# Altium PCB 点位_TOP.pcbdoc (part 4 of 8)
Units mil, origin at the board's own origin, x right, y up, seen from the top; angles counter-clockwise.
Board outline 5129 x 4161 mil, 8 copper layers (Top Layer, GND1, 内层2, VCC, 内层4, Inner5, GND2, Bottom Layer); 288 components, 452 nets, 2040 pads, 1119 vias.
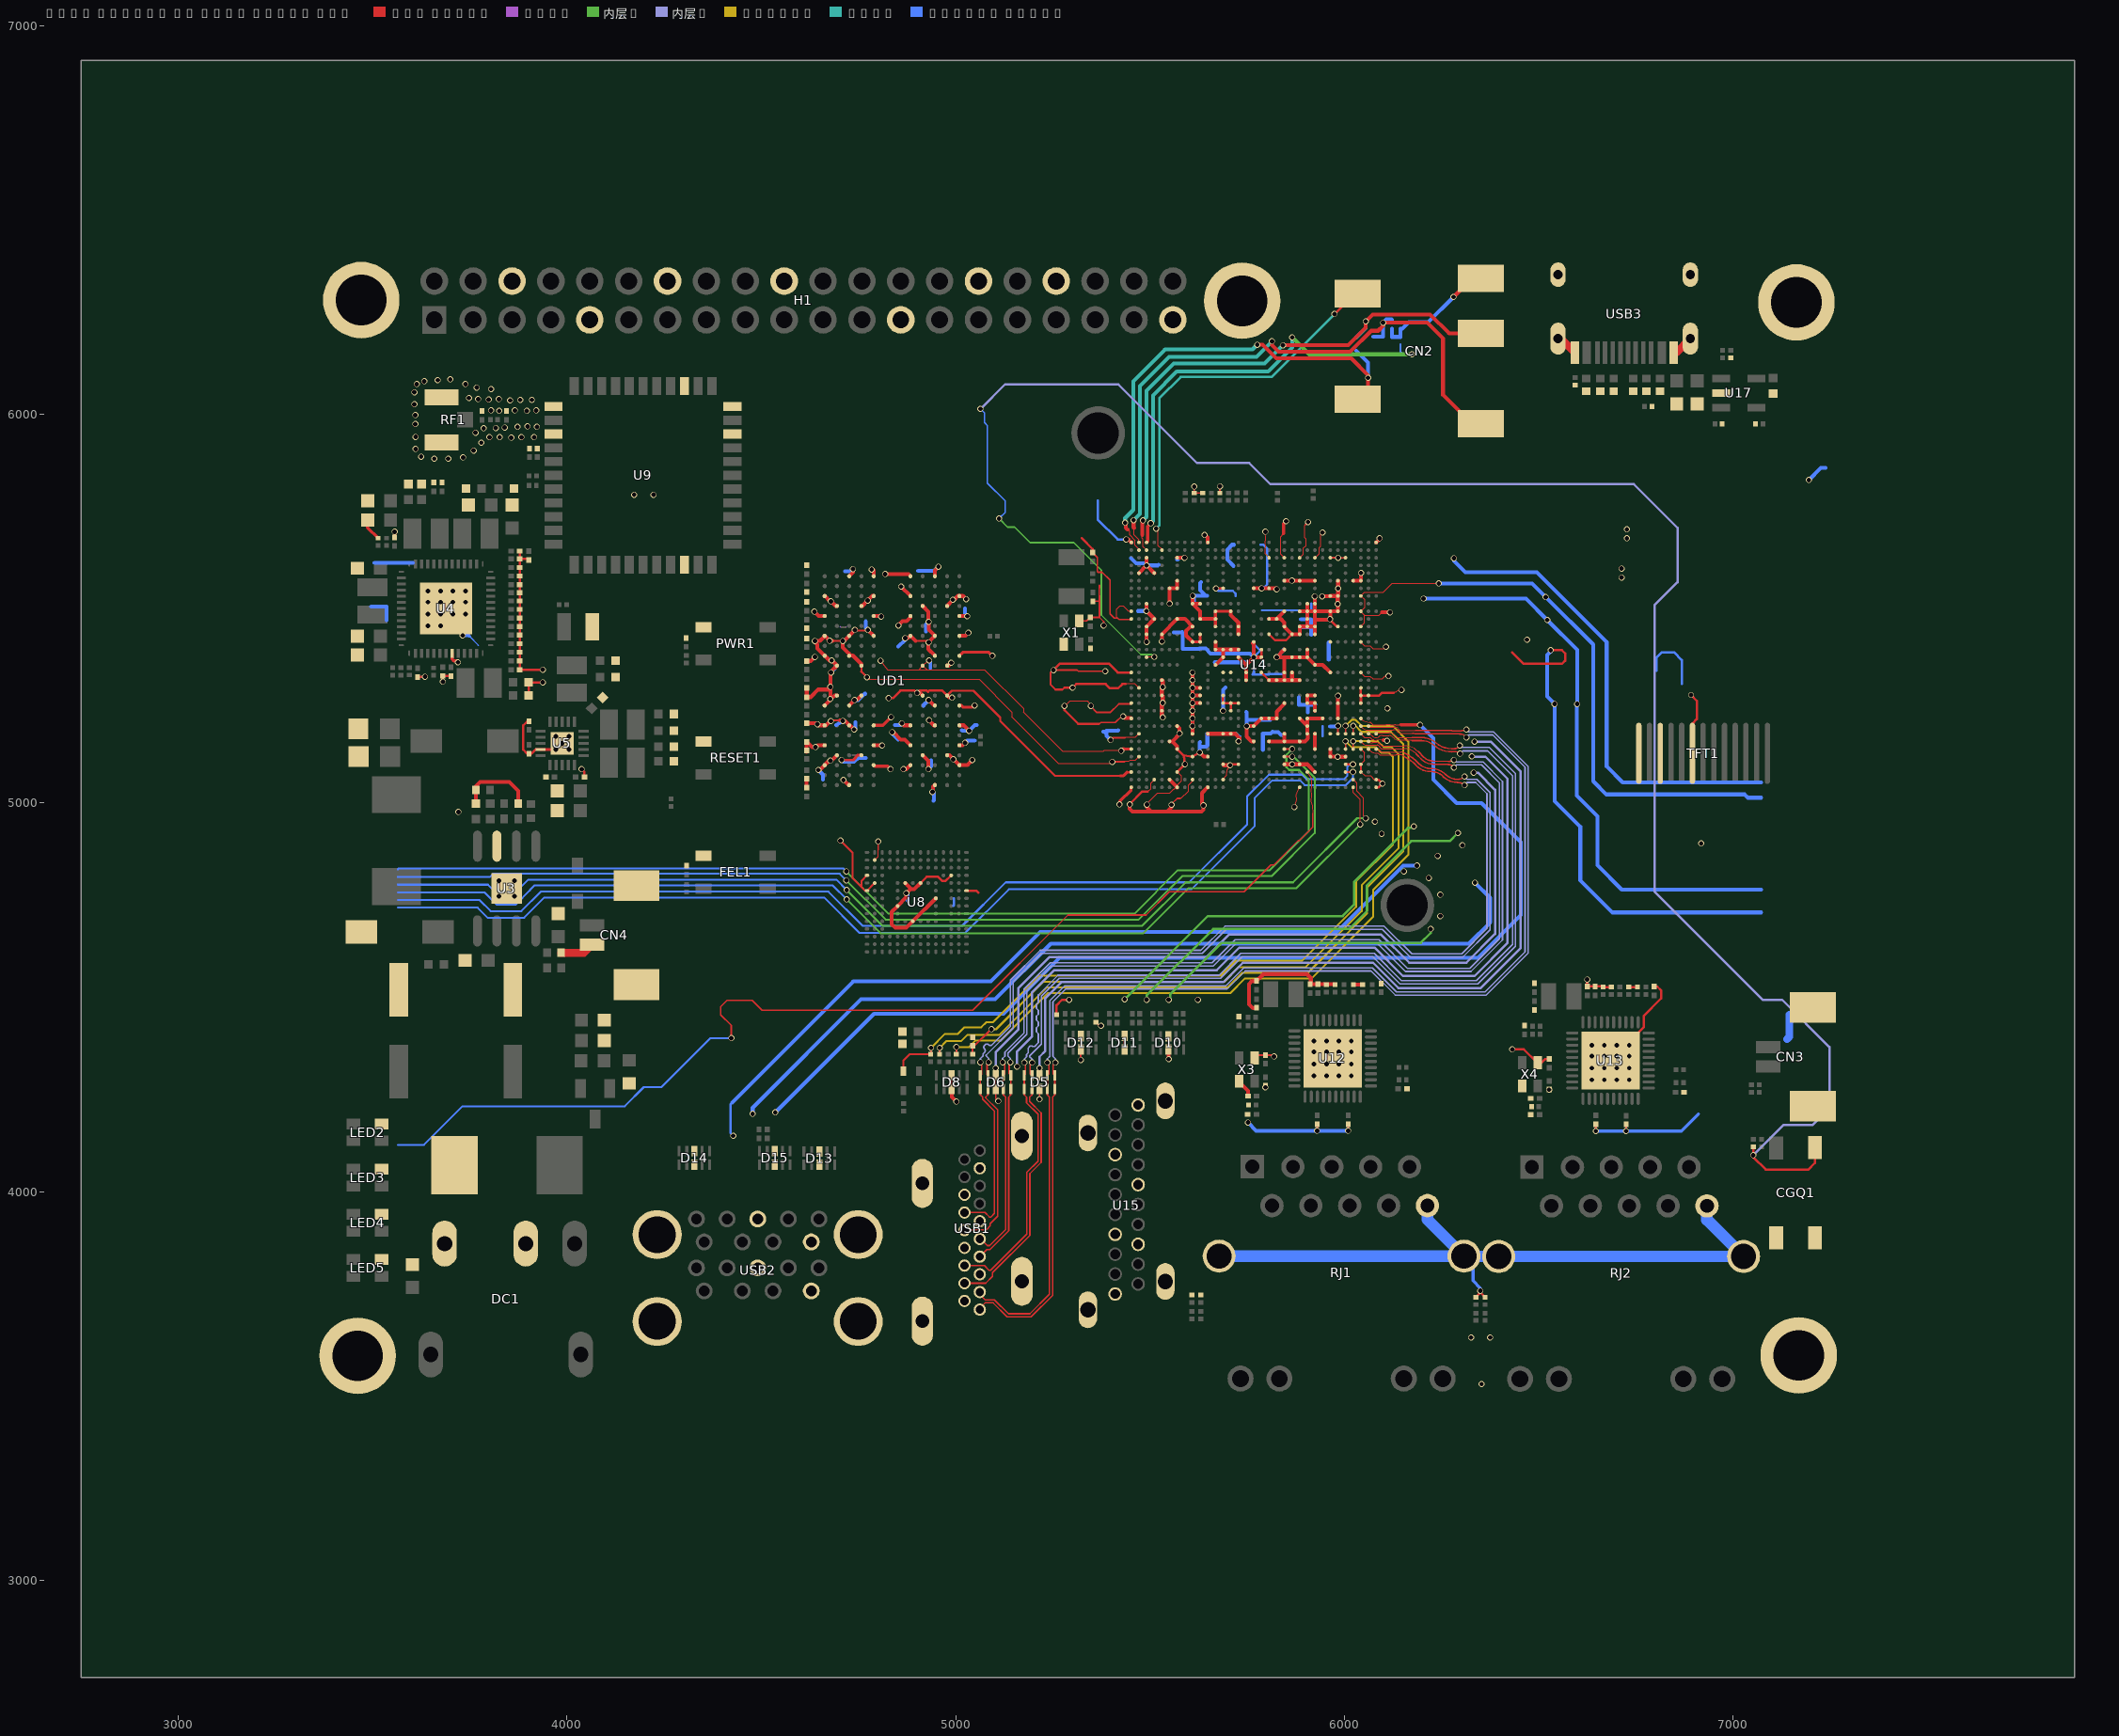
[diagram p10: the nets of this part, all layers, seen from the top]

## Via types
v1: diameter 15.75, hole 11.8, Top Layer to Bottom Layer, 496 vias
v2: diameter 15.7, hole 11.8, Top Layer to Bottom Layer, 335 vias
v3: diameter 15.75, hole 11.81, Top Layer to Bottom Layer, 279 vias
v4: diameter 24, hole 12, Top Layer to Bottom Layer, 9 vias

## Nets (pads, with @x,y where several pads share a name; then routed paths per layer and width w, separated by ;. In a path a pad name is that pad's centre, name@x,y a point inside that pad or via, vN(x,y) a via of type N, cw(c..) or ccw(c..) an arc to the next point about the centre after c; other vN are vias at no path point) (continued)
GND: C1.1 C2.1 C3.1 C5.1 C6.1 C7.1 C8.1 C10.2 C11.2 C12.2 C15.1 C16.1 C17.2 C18.1 C25.1 C27.1 C28.1 C31.1 C33.1 C35.1 C43.2 C44.1 C45.1 C51.2 C52.2 C53.2 C54.2 C55.2 C59.2 C60.1 C61.2 C62.1 C63.2 C64.1 C65.2 C66.1 C69.2 C70.1 C71.2 C72.1 C73.2 C74.1 C80.1 C81.1 C87.1 C88.2 C89.1 C95.1 C96.1 C97.1 C98.1 C99.1 C100.1 C101.1 C131.1 C136.1 C139.1 C140.1 C146.1 C147.2 C148.1 C149.1 C150.1 C157.1 C158.1 C159.1 C160.1 C179.1 C180.1 C189.1 C210.1 C218.1 C221.1 C222.1 C244.1 C245.1 C249.2 C250.2 C251.1 C252.1 C253.2 C254.2 C256.2 C257.1 C258.2 C259.1 C260.2 C261.2 C262.2 C263.2 C264.2 C265.2 C266.2 C267.2 C268.1 C269.2 C270.2 C271.2 C272.2 C273.2 C274.2 C275.1 C280.1 C281.1 C282.1 C283.1 C284.1 C290.1 C291.1 C292.1 C293.1 CGQ1.1 CGQ1.2 CN3.3 CN3.4 CN4.1 CN4.3 CN4.4 D2.1 D4.1 D5.3 D5.8 D6.3 D6.8 D8.3 D8.8 D10.3 D10.8 D11.3 D11.8 D12.3 D12.8 D13.3 D13.8 D14.3 D14.8 D15.3 D15.8 D24.1 D25.1 D26.1 D27.1 D30.1 D31.1 DC1.2 DC1.3 FEL1.1 H1.6 H1.9 H1.14 H1.20 H1.25 H1.30 H1.34 H1.39 LED1.2 LED2.2 LED3.2 LED4.2 LED5.2 pad.54 PWR1.1 R2.1 R6.1 R7.2 R8.1 R13.1 R33.1 R34.1 R35.1 R60.1 R62.1 R82.1 R85.1 R86.1 R93.1 R94.1 R95.1 R96.1 R100.1 R103.1 R104.1 R111.1 R112.1 R113.1 R114.1 R117.2 R118.1 R121.1 R129.1 R130.1 RESET1.1 RF1.2 RF1.3 RJ1.P10 RJ1.SHIELD0 RJ1.SHIELD1 RJ2.P10 RJ2.SHIELD0 RJ2.SHIELD1 TFT1.8 TFT1.11 TFT1.13 U1.2 U2.2 U3.7 U3.9 U4.8 U4.53 U5.9 U5.21 U8.A6 U8.C4 U8.E7 U8.G5 U8.H10 U8.J5 U8.K8 U8.N2 U8.N5 U8.P4 U8.P6 U9.1 U9.3 U9.20 U9.31 U9.33 U9.36 U12.41 U13.41 U14.A1 U14.A32 U14.A33 U14.AA7 U14.AA15 U14.AA16 U14.AA18 U14.AA21 U14.AA22 U14.AA26 U14.AA30 U14.AA32 U14.AB10 U14.AB11 U14.AB12 U14.AB14 U14.AB15 U14.AB17 U14.AC1 U14.AC26 U14.AC29 U14.AC33 U14.AD9 U14.AD11 U14.AD13 U14.AD14 U14.AD20 U14.AD21 U14.AD22 U14.AE9 U14.AE12 U14.AE14 U14.AE18 U14.AE19 U14.AE20 U14.AE21 U14.AE22 U14.AE23 U14.AE24 U14.AE25 U14.AE26 U14.AE29 U14.AE32 U14.AG3 U14.AG6 U14.AG7 U14.AG11 U14.AG25 U14.AG28 U14.AG31 U14.AG33 U14.AH7 U14.AH9 U14.AH27 U14.AH32 U14.AJ13 U14.AJ19 U14.AJ21 U14.AJ23 U14.AK5 U14.AK11 U14.AK32 U14.AL3 U14.AL9 U14.AL12 U14.AL13 U14.AL14 U14.AM5 U14.AM20 U14.AM26 U14.AM29 U14.AN1 U14.AN10 U14.AN11 U14.AN18 U14.AN22 U14.AN24 U14.AN28 U14.AN31 U14.AN33 U14.B21 U14.C6 U14.C8 U14.C10 U14.C12 U14.C14 U14.C18 U14.C20 U14.C21 U14.C22 U14.C24 U14.C26 U14.C28 U14.C30 U14.C31 U14.D6 U14.E3 U14.E29 U14.F6 U14.F8 U14.F10 U14.F12 U14.F22 U14.F24 U14.G3 U14.G8 U14.G10 U14.G14 U14.G18 U14.G26 U14.G28 U14.G29 U14.H24 U14.J3 U14.J6 U14.J9 U14.J10 U14.J12 U14.J13 U14.J17 U14.J21 U14.J22 U14.J23 U14.J26 U14.J28 U14.J31 U14.K9 U14.K10 U14.K11 U14.K12 U14.K15 U14.K16 U14.K21 U14.K22 U14.K24 U14.K25 U14.K26 U14.L3 U14.L6 U14.L10 U14.L12 U14.L13 U14.L16 U14.L19 U14.L24 U14.L27 U14.L30 U14.L33 U14.M13 U14.M16 U14.M18 U14.M19 U14.N3 U14.N6 U14.N10 U14.N12 U14.N15 U14.N18 U14.N19 U14.N22 U14.N26 U14.N27 U14.N30 U14.P11 U14.P16 U14.P19 U14.P24 U14.R3 U14.R7 U14.R11 U14.R13 U14.R19 U14.R24 U14.R27 U14.T15 U14.T16 U14.T18 U14.T24 U14.U7 U14.U14 U14.U16 U14.U25 U14.U27 U14.V18 U14.V19 U14.W12 U14.W13 U14.W15 U14.W16 U14.W22 U14.W27 U14.W30 U14.Y10 U14.Y15 U14.Y18 U14.Y22 U14.Y23 U14.Y26 U15.2 U15.5 U15.8 U15.11 U15.16 U15.19 U15.21 U15.22 U15.23 U15.24 U17.2 UD1.A3 UD1.A10 UD1.AB3 UD1.AB5 UD1.AB8 UD1.AB10 UD1.C1 UD1.C5 UD1.C8 UD1.C12 UD1.D2 UD1.D4 UD1.D9 UD1.D11 UD1.E1 UD1.E5 UD1.E8 UD1.E12 UD1.G1 UD1.G3 UD1.G5 UD1.G8 UD1.G10 UD1.G12 UD1.J1 UD1.J3 UD1.J10 UD1.J12 UD1.K2 UD1.K4 UD1.K9 UD1.K11 UD1.N2 UD1.N4 UD1.N9 UD1.N11 UD1.P1 UD1.P3 UD1.P10 UD1.P12 UD1.T1 UD1.T3 UD1.T5 UD1.T8 UD1.T10 UD1.T12 UD1.V1 UD1.V5 UD1.V8 UD1.V12 UD1.W2 UD1.W4 UD1.W9 UD1.W11 UD1.Y1 UD1.Y5 UD1.Y8 UD1.Y12 USB1.2 USB1.5 USB1.8 USB1.11 USB1.14 USB1.17 USB1.20 USB2.4 USB2.7 USB2.13 USB2.16 USB2.19 USB2.20 USB2.21 USB2.22 USB3.12 USB3.13 USB3.14 USB3.15 USB3.A1B12 USB3.B1A12 X1.2 X1.4 X3.2 X3.4 X4.2 X4.4 | length 43526.2
  Top Layer w3: v3(4771.91,5323.56) 4778.17,5317.3 4790.29,5317.3 4790.79,5316.8 5062.09,5316.8 5144.92,5233.97 5144.92,5221.97 5265.92,5100.97 5397.92,5100.97 v3(5402.92,5105.97) ; U8.N2@4791.73,4853.27 4801,4862.53 4801,4879 ; v3(4806.92,5365.97) 4824.86,5342.71 4906.66,5342.71 ; v3(4931.79,5366.86) UD1.N4@4915.28,5353.26 ; v3(5279.92,5249.97) 5294,5263 5339,5263 v3(5347.92,5249.97) ; 5417,5475.76 5413,5479.76 5413,5498 5421,5506 5433,5506 5445.73,5493.27 U14.AN10@5452.02,5493.27 ; v3(5426.17,5134.47) 5424.42,5134.47 5423.92,5134.97 5381.92,5134.97 5378.92,5131.97 5276.92,5131.97 5174.92,5233.97 5174.92,5242.97 5074.62,5343.27 5068,5342.71 4926.58,5342.71 ; 5433.78,5106.24 5444.61,5106.24 5447.62,5109.25 5447.74,5109.3 5461.54,5109.3 U14.AM29@5471.37,5119.12 ; 5435.01,5168.31 5461.51,5168.31 U14.AM26@5471.37,5178.17 ; 5437.37,5306.11 5461.54,5306.11 U14.AM20@5471.37,5296.28 ; v3(5491.92,4995.97) 5491.92,4997.97 5517.99,5024.05 5550,5024.05 5559.93,5033.97 5560.09,5033.97 5566.5,5040.38 U14.AG33@5569.8,5040.38 ; 5493.92,5028.97 5500.88,5035.93 5500.88,5050.2 U14.AK32@5510.74,5060.06 ; 5569.8,5045.83 5579.62,5055.65 5579.62,5069.93 U14.AG31@5569.8,5079.75 ; 5576.94,5012 5580.16,5012 5599.3,5031.14 5599.3,5046 5609.17,5055.87 U14.AE32@5609.17,5060.06 ; U14.AA32@5688.23,5060.36 5697.5,5071.48 5698.19,5085.27 v3(5706.21,5097.25) ; v1@5796.92,5704.45 5796.92,5698.08 v1(5797,5698) 5798.02,5679.35 5796.7,5669.97 5796.7,5667.55 5797.21,5660.81 5796.63,5652.88 5796.63,5641.76 U14.R3@5805.97,5632.41 ; 5844.08,5693 5836.22,5685.13 5836.22,5640.38 U14.N3@5845.59,5631.01 ; v1(5871,4990) 5877.52,5008.07 5876.71,5021.27 5878.56,5027.18 U14.L33@5885.17,5040.39 ; U14.L3@5885.31,5630.49 5895.08,5640.26 5895.08,5655.52 5901.88,5662.32 5901.88,5678.69 5898.1,5682.47 5898.1,5714.19 v1@5901.15,5717.24 ; U14.J3@5924.39,5631.01 5934.2,5640.82 5934.2,5655.73 5938.58,5660.11 5938.58,5690.58 v1(5944,5696) ; U14.C26@6042.49,5178.21 6052.24,5168.46 6066.53,5168.46 6072.36,5162.63 cw(c6072.36,5125.86) 6076.05,5162.44 ccw(c6081.58,5178.89) 6083.05,5161.6 cw(c6091.02,5068.2) v1(6110,5160) ; U14.C18@6042.49,5335.71 6052.29,5325.91 6066.46,5325.91 6073.03,5319.34 6097.59,5319.34 6104.94,5326.69 v1(6113.42,5326.69) ; U14.C10@6042.49,5493.21 6052.29,5483.41 ; U14.C31@6042.57,5079.88 6052.45,5070 6067,5070 6076.8,5060.2 U14.A32@6081.94,5060.2 ; U14.C28@6042.57,5138.93 6051.92,5129.57 ; U14.C12@6042.57,5453.9 6052.12,5463.46 6052.12,5483.24 6052.29,5483.41 ; U14.C10@6042.57,5493.27 6052.49,5503.19 6052.49,5522.51 U14.C8@6042.57,5532.43 ; U14.C8@6042.57,5532.64 U14.C8@6042.57,5532.43 ; U14.C30@6042.58,5099.56 6052,5108.99 6052.43,5119.97 6051.92,5129.57 ; U14.C14@6042.99,5413.27 6051.68,5404.59 6066.16,5404.59 6073.23,5397.52 6102.52,5397.52 v1(6107,5402) ; U14.C24@6043.86,5216.74 ccw(c6065.87,5238.75) 6064.56,5207.65 cw(c6057.14,5031.33) 6067.48,5207.51 6073.32,5201.67 6107.25,5201.67 cw(c6107.25,3703.56) 6118.2,5201.63 6128.93,5201.63 cw(c6128.93,5180.28) 6131.45,5201.48 ccw(c6138.2,5258.08) 6144.89,5201.47 ; 6051.92,5129.7 6051.92,5129.57 ; 6052,5129.49 6051.92,5129.57 ; 6096.82,5490.65 6089.58,5483.41 6052.29,5483.41 ; 6099.89,5162.63 6100.74,5161.78 ; 6127.09,5284 6128.47,5285.38 6133.38,5285.38 6139,5291 v1(6147,5291) ; 6145.32,5202 6194,5202 v2(6195,5201) ; v2(6243,5565) 6123.3,5565 6100.52,5542.23 6052.36,5542.23 U14.C8@6042.57,5532.43 ; 4906.66,5342.71 UD1.N4@4915.28,5353.26 ; 4906.66,5342.71 4926.58,5342.71 ; UD1.N4@4915.28,5353.26 4926.58,5342.71
  Top Layer w4: 4801,4879 v2(4801,4901) ; v1(5103,4318) D6.3@5102.99,4299.33 D6.8@5102.99,4264.67 5102.99,4240.01 v1(5110,4233) ; v1(5216,4238) D5.8@5215.99,4264.67 ; D5.3@5215.99,4299.33 v1(5216,4318) ; v3(5251.92,5341.97) 5312.92,5341.97 5315.92,5338.97 v3(5385,5339) ; X1.4@5318,5468.46 5337.17,5468.46 C99.1@5346.35,5477.65 5370.11,5477.65 ; C101.1@5352.45,5644.32 5365,5631.77 5365,5594.76 5366,5593.76 5377,5593.76 5397,5573.76 5397,5486.76 5408,5475.76 5417,5475.76 5421,5471.76 5450.19,5471.76 U14.AN11@5452.02,5473.58 ; C100.1@5353,5519.26 5369.77,5519.26 5370.03,5519 ; 5368.77,5203.54 5370.19,5203.54 5373.72,5207.08 5411.03,5207.08 5426.92,5222.97 v3(5430.92,5222.97) ; 5370,5560 ccw(c8759.66,5542.39) 5369.99,5526 cw(c-4631.6,5477.64) 5370.03,5519.01 ; v1(5381,5456.76) 5381,5466.76 5370.11,5477.65 ; v3(5555.44,4995.51) 5555.44,4997.34 5570.09,5012 5576.94,5012 ; U14.AG33@5569.8,5040.38 5569.8,5045.83 ; v1(5614,5814) R35.1@5614,5797.51 R33.1@5636,5797.51 ; R34.1@5680,5797.51 v1(5680,5815) ; X3.4@5769,4342 5778.5,4351.5 C252.1@5797,4351.5 5815.5,4351.5 v1(5819,4348) ; U14.G3@5963.83,5631.06 v1@5983.94,5631.06 ; v1(5984,5631) U14.E3@6003.14,5631 ; 5370.03,5519 cw(c-4631.89,5477.64) 5370.11,5477.64
  Top Layer w4.5: v3(5347.92,5249.97) 5347.92,5248.97 5363.92,5232.97 5397.92,5232.97 5419.94,5255 U14.AN22@5449.77,5255 ; U14.AN22@5451.69,5256.91 U14.AN22@5449.77,5255 ; U14.AN22@5452.02,5257.04 5449.98,5255 U14.AN22@5449.77,5255
  Top Layer w5: D15.8@4534.99,4069.67 D15.3@4534.99,4104.33 ; D13.8@4649.39,4069.01 D13.3@4649.39,4103.67 ; v3@4679.24,5212.49 v3@4702.79,5212.49 ; v3@4683.54,5417.29 4709.6,5417.29 v3(4709.92,5416.97) ; v2(4704,4903) 4735,4872 4735,4807 4758,4784 ; v3(4740.72,5444.96) 4742.1,5443.58 4772.51,5443.58 v3(4774.25,5445.32) ; 4757.66,5337.81 UD1.N9@4757.66,5353.63 ; U8.P4@4772.05,4813.9 4758,4799.85 4758,4784 ; U8.N5@4791.73,4794.22 U8.P6@4772.05,4774.52 4767.48,4774.52 4758,4784 ; 4897.07,5416.97 4927.1,5416.97 v3(4930.92,5413.15) ; UD1.K2@4978.13,5276.85 4990.25,5288.97 5045.92,5288.97 5114.92,5219.97 5114.92,5210.97 5255.92,5069.97 5424.21,5069.97 ; D8.3@4990.01,4264.67 D8.8@4990.01,4299.33 ; v3(5251.92,5341.97) 5250.92,5341.97 5243.92,5334.97 5243.92,5304.97 5256.92,5291.97 5274.91,5291.97 5279.66,5296.72 v3(5300.92,5296.72) ; v1(5322.01,4339) D12.3@5322.01,4365.67 D12.8@5322.01,4400.33 ; R60.1@5364.51,4436.49 R60.1@5361,4436.49 5370.49,4427 v1(5374,4427) ; v3(5398.92,5161.97) 5404.66,5167.71 5434.41,5167.71 5435.01,5168.31 ; v3(5402.92,5105.97) 5405.56,5105.98 5405.82,5106.24 5433.78,5106.24 ; D11.8@5434.72,4365.9 D11.3@5434.72,4400.56 ; D10.8@5547.14,4365.48 D10.3@5547.14,4400.14 ; v1@5901.15,5717.24 v1(5906.65,5722.74) ; v1(5930,4157) C267.2@5930,4174 ; v1(6010,4157) C266.2@6010,4174 ; U14.C31@6042.57,5079.88 U14.C30@6042.58,5099.56 ; v1(6647,4156) C275.1@6647,4173.5 ; v1(6725,4156) C272.2@6725,4173
  Top Layer w6: C95.1@3616,5324.5 3616.5,5325 v1(3635,5325) ; C11.2@3681,5327 C11.2@3681.28,5326.72 ; v1(3681.28,5312) C11.2@3681.28,5326.72 ; C43.2@3701.75,5326.72 C11.2@3681.28,5326.72 ; C66.1@3879,5648 C64.1@3879,5628 ; C15.1@3902.01,5277.28 C16.1@3902.01,5310.28 v2(3938,5310.28) ; C35.1@3902,5625.5 3899.5,5628 C64.1@3879,5628 ; C73.2@3903,5210.5 3898.5,5210.5 3888,5200 3888,5137 3898,5127 C88.2@3903,5127 3909,5127 3919.74,5137.74 U5.9@3932.43,5137.74 ; v2(3938,5343) C51.2@3879,5343 C52.2@3879,5366 C55.2@3879,5388 C53.2@3879,5410 C54.2@3879,5432 C59.2@3879,5454 C61.2@3879,5476 C17.2@3879,5498 C63.2@3879,5520 C65.2@3879,5541 C60.1@3879,5562 C62.1@3879,5584 C12.2@3879,5606 C64.1@3879,5628 ; v2(4038,5087) 4045,5080 C69.2@4045,5067 ; v3(4706.92,5110.97) 4732,5110 4736.92,5110.97 ; 4757.66,5337.81 v3(4771.91,5323.56) ; v3(4827.92,5269.97) 4838.92,5269.97 4858.25,5289.3 4894.59,5289.3 v3(4900.92,5282.97) 4907.25,5289.3 4925.59,5289.3 4928.92,5285.97 4932.25,5289.3 4965.68,5289.3 UD1.K2@4978.13,5276.85 ; U8.G5@4909.85,4794.22 4925.63,4810 4955,4810 4966,4799 4973.69,4799 U8.C4@4988.59,4813.9 ; U8.A6@5027.95,4774.52 5053.48,4774.52 5059,4769 ; v3(5251.92,5341.97) 5268.94,5359 5394,5359 5417.22,5335.78 U14.AN18@5452.02,5335.78 ; R62.1@5260,4455.51 5260,4480 5274,4494 v2(5292,4494) ; v3(5279.92,5249.97) 5279.92,5238.97 5315.35,5203.54 5368.77,5203.54 ; v3(5300.92,5296.72) 5310.17,5305.97 5385.92,5305.97 5396.92,5294.97 5417.97,5294.97 5429.11,5306.11 5437.37,5306.11 ; 5325,5681 5352.45,5653.55 C101.1@5352.45,5644.32 ; 5440.71,5078.75 U14.AN31@5450.69,5078.75 ; v3(5448.16,4996.51) 5448.44,4996.79 5448.44,4998.01 5479.4,5028.97 5493.92,5028.97 ; U14.AG31@5570.13,5079.87 v3(5589.92,5099.97) 5587,5122 ; U14.AG28@5570.13,5138.93 5587,5122 ; v3(5627.92,5129.97) U14.AE29@5609.5,5119.25 5587,5122 ; v2(5670,5552) 5687.92,5552 U14.AA7@5688.24,5552.32 ; U14.AA21@5688.24,5276.73 U14.AA22@5688.24,5257.04 U14.Y22@5707.92,5257.04 ; v3(5706.21,5097.25) 5708.46,5099.51 U14.W30@5727.3,5099.51 ; U14.Y23@5707.92,5237.36 U14.Y22@5707.92,5257.04 ; U14.W22@5727.61,5257.04 U14.Y22@5707.92,5257.04 ; U14.T18@5786.67,5335.78 U14.R19@5806.35,5316.1 ; U14.T16@5786.67,5375.16 U14.T15@5786.67,5394.84 ; U14.R13@5806.35,5434.21 5821.56,5419 5850.2,5419 U14.M13@5865.41,5434.21 ; v2(5963,5473) 5963,5472 5981.1,5453.9 U14.F12@5983.52,5453.9 ; U14.C20@6042.57,5296.41 U14.C21@6042.57,5276.73 U14.B21@6062.26,5276.73 6089.73,5276.73 6097,5284 6127.09,5284 ; U14.A33@6081.94,5040.51 6088.51,5040.51 v1(6098,5050) 6087.8,5060.2 U14.A32@6081.94,5060.2 ; R114.1@6338.37,3728.63 6350,3740.26 v1@6350,3740.99 ; v1(6350,3745) v1@6350,3740.99 ; R112.1@6362.37,3728.63 v1@6350,3740.99 ; v2(6432,4366) 6462,4366 6496,4332 6507.49,4332 6516.99,4341.5 C259.1@6527,4341.5 ; 6432,5387 6461,5358 6560,5358 6568,5366 6568,5385 6560,5393 v2(6531,5393) ; C258.2@6625,4528 C256.2@6645,4528 6664.51,4528 R111.1@6666,4526.51 R113.1@6687,4526.51 ; U13.41@6684.91,4337.51 6684.91,4337.91 6770,4423 6770,4452 6815,4497 6815,4518 6805.62,4527.38 C274.2@6797.2,4527.38 ; R104.1@6732,4526.51 R100.1@6754,4526.51 ; v2(6892,5278) 6907,5263 6907,5216 6895.44,5204.44 TFT1.8@6895.44,5127.67
  Top Layer w7: C258.2@6625,4528 v2(6625,4546)
  Top Layer w8: C291.1@3487.47,5728 3487.47,5708.5 R13.1@3514.47,5681.51 ; C45.1@3557,5683.5 v2(3557,5698) ; U4.8@3704.86,5385.61 3704.86,5370.14 3709,5366 3715.97,5366 v1(3719.75,5362.22) ; U5.9@3932.43,5137.74 v1(3972.09,5137.74) v1(3987.84,5153.49) ; 4736.92,5110.97 4749.26,5123.31 UD1.D9@4757.66,5123.31 ; UD1.C8@4789.16,5097.72 4791.91,5094.97 4824.92,5094.97 v3(4832.92,5086.97) ; UD1.G8@4789.16,5200.08 4813.03,5200.08 v3(4833.92,5220.97) ; UD1.P1@5009.63,5379.22 5018.38,5387.97 5085.25,5387.97 v3(5094.5,5378.72) ; UD1.J1@5012.33,5251.26 5015.13,5251.26 5019.9,5246.49 5042.44,5246.49 5046.92,5250.97 5048.67,5250.97 v3(5048.92,5251.22) ; v3(5421.61,4996.51) 5422.61,4997.51 5422.61,5004.66 5451.29,5033.34 5451.29,5039.45 5451.69,5039.84 U14.AN33@5451.69,5040.38 ; 5424.21,5069.97 5431.93,5069.97 5440.71,5078.75 ; v3@5431.97,5138.8 U14.AN28@5451.69,5138.8 ; U14.AE14@5609.5,5414.53 U14.AD14@5629.18,5414.53 ; U14.AD14@5629.18,5414.53 U14.AD13@5629.18,5434.21 ; U14.AB12@5668.55,5453.9 U14.AB11@5668.55,5473.58 U14.AB10@5668.55,5493.27 U14.Y10@5707.92,5493.27 ; 5844.08,5693 5844.08,5719.08 v1(5850,5725) ; U14.C21@6041.87,5277.3 6042.57,5276.6 U14.C22@6042.57,5256.6 ; 6145.32,5202 6146.32,5201 v2(6195,5201)
  Top Layer w10: C10.2@3766,4999.01 R7.2@3766,5034 3766,5043 3777.01,5054.01 3851.99,5054.01 3874.85,5031.15 R8.1@3874.85,4998.18 ; C157.1@4616.92,5038.47 C131.1@4616.92,5060.47 ; C146.1@4616.92,5131.47 4616.92,5158.47 4631.42,5143.97 v3(4639.84,5143.97) 4644.77,5148.9 UD1.E12@4663.17,5148.9 ; C147.2@4616.92,5205.47 4641.65,5205.47 v3(4644.53,5202.59) 4647.04,5200.08 4666.83,5200.08 v3@4677.51,5210.76 ; C149.1@4617,5296.5 C148.1@4617,5272.5 4627.5,5272.5 4647,5292 4670.86,5292 v3(4677.84,5298.97) ; C158.1@4617,5365.5 4627.44,5365.5 v3(4637.92,5375.97) ; v3(4636.87,5492.24) 4647.53,5481.58 UD1.V12@4663.17,5481.58 ; v3(4646.77,5084.95) 4650.4,5084.95 4672.74,5107.29 4676.24,5107.29 v3(4677.92,5108.97) 4680.34,5108.97 UD1.D11@4694.68,5123.31 ; UD1.J12@4663.17,5251.3 4677.68,5265.81 v3(4677.68,5267.64) ; UD1.Y12@4663.17,5532.76 4676.82,5519.11 v3(4679.3,5519.11) 4691.24,5507.17 UD1.W11@4694.67,5507.17 ; v3(4676.21,5417.22) 4676.21,5417.36 4663.17,5430.4 4663.17,5429.22 4650.92,5416.97 v3(4637.92,5416.97) 4637.92,5413.97 4644.67,5407.22 4644.67,5397.73 4675.41,5366.99 v3(4681.32,5366.99) 4694.68,5353.63 4679.84,5338.79 v3(4679.84,5335.97) 4677.84,5333.97 v3(4677.84,5298.97) ; v3@4676.28,5417.29 v3@4683.54,5417.29 ; v3(4679.27,5210.76) v3@4677.51,5210.76 ; v3@4679.24,5212.49 v3@4677.51,5210.76 ; UD1.K11@4694.67,5276.85 4688.72,5276.85 4679.84,5267.97 4678.28,5267.97 4677.95,5267.64 v3(4677.68,5267.64) ; v3@4702.79,5212.49 4708.51,5212.49 v3(4709.98,5211.02) 4715.22,5211.02 4726.16,5200.08 4727.81,5200.08 v3(4738.92,5188.97) ; v3(4711.57,5059.21) 4724.24,5046.54 UD1.A10@4726.16,5046.54 ; UD1.J10@4726.16,5251.26 v3(4739.91,5265.01) 4740.87,5265.97 4746.79,5265.97 UD1.K9@4757.67,5276.85 ; UD1.AB10@4726.16,5583.94 4735.92,5593.7 v3(4735.92,5601.97) ; v3@4742.75,5446.99 v3(4740.72,5444.96) 4713.05,5417.29 4710.24,5417.29 v3(4709.92,5416.97) 4709.92,5399.97 4726.16,5383.73 4726.16,5379.22 4735.67,5379.22 4757.66,5357.23 UD1.N9@4757.66,5353.63 ; UD1.W9@4757.66,5507.17 4760.08,5507.17 v3(4773.92,5521.01) 4785.67,5532.76 UD1.Y8@4789.16,5532.76 ; v3(4774.25,5445.32) UD1.T8@4789.17,5430.4 ; v3(4783.92,5600.97) 4786.92,5600.97 4789.17,5598.72 UD1.AB8@4789.17,5583.94 ; UD1.E8@4789.17,5148.9 4809.99,5148.9 v3(4810.92,5147.97) ; UD1.V8@4789.17,5481.58 4803.31,5481.58 4804.92,5479.97 4806.92,5479.97 4807.06,5479.83 v3(4808.4,5479.83) ; v3(4818.92,5588.97) 4878.61,5588.97 UD1.AB5@4883.64,5583.94 ; v3(4836.92,5181.97) 4839.92,5181.97 4858.92,5162.97 4869.57,5162.97 UD1.E5@4883.64,5148.9 ; v3(4852.92,5456.97) 4852.92,5457.72 4863.17,5467.97 4873.64,5467.97 4883.64,5477.97 UD1.V5@4883.64,5481.58 ; v3(4859.92,5556.97) 4859.92,5556.48 UD1.Y5@4883.64,5532.76 ; v3(4861.84,5204.97) 4866.73,5200.08 UD1.G5@4883.64,5200.08 ; v3(4865.92,5086.97) 4872.89,5086.97 UD1.C5@4883.64,5097.72 ; v3(4870.1,5423.94) 4877.18,5423.94 4883.64,5430.4 4897.07,5416.97 ; U8.J5@4870.55,4794.14 4883.69,4781 ; v3(4900.92,5282.97) 4909.02,5282.97 UD1.K4@4915.14,5276.85 ; U8.G5@4909.85,4794.22 4893.63,4778 4886.69,4778 4883.69,4781 ; UD1.D4@4915.14,5123.31 4929.92,5108.53 v3(4929.92,5086.97) ; UD1.W4@4915.14,5507.17 4929.96,5492.35 4929.96,5466.93 v3(4930.92,5465.97) 4930.67,5465.72 4930.67,5446.37 4946.64,5430.4 4931.03,5414.79 4931.03,5413.26 v3(4930.92,5413.15) 4929.84,5412.07 4929.84,5395.97 UD1.P3@4946.59,5379.22 ; v3(4930.92,5264.97) 4944.63,5251.26 UD1.J3@4946.64,5251.26 ; v3(4931.92,5212.97) 4931.92,5211.96 4943.8,5200.08 UD1.G3@4946.64,5200.08 ; v3(4940.28,5028.72) 4941.92,5030.36 4941.92,5041.81 UD1.A3@4946.64,5046.53 ; UD1.AB3@4946.64,5583.94 4946.64,5598.69 v3(4955.92,5607.97) ; U8.E7@4949.22,4754.85 U8.H10@4890.15,4695.78 4873.37,4679 4844.69,4679 4835.69,4688 4835.69,4719.69 4850.78,4734.78 U8.K8@4850.78,4735.15 4873,4757.37 v2(4873,4768) 4883.69,4778.69 4883.69,4781 ; UD1.D2@4978.13,5123.31 4984.03,5123.31 4994.03,5113.31 4994.03,5112.97 v3(4994.29,5112.71) 4994.64,5112.71 5009.63,5097.72 5030.66,5097.72 5042.92,5109.98 v3(5042.92,5110.64) ; UD1.K2@4978.13,5276.85 4982.65,5272.33 4989.67,5272.33 v3(4991,5271) ; UD1.N2@4978.13,5353.63 4981.58,5353.63 v3(4988.92,5360.97) ; UD1.W2@4978.13,5507.17 4992.84,5521.88 v3(4992.84,5522.97) 4995.84,5522.97 5005.63,5532.76 5018.75,5532.76 v3(5027.18,5524.33) ; D8.3@4990.01,4264.67 4990.01,4243.99 v2(5002,4232) ; UD1.E1@5009.63,5148.9 5018.42,5148.9 v3(5024.22,5154.7) ; UD1.G1@5009.63,5200.08 5020.81,5200.08 v3(5034.92,5185.97) ; UD1.T1@5009.63,5430.4 5025.35,5430.4 v3(5033,5438.05) ; UD1.V1@5009.63,5481.58 5024.15,5481.58 5024.92,5480.81 5029.08,5480.81 5029.4,5480.49 v3(5029.92,5480.49) ; v3(5426.17,5134.47) 5427.42,5134.47 5430.11,5137.16 5430.33,5137.16 v3@5431.97,5138.8 ; v3(5430.92,5222.97) 5435.5,5218.39 5450.84,5218.39 U14.AN24@5451.69,5217.54 ; v1(5439,5678) 5444.45,5678 U14.AN1@5452.02,5670.43 ; v3(5448.16,4996.51) 5448,4996.36 5448,4985 5455.03,4977.97 5502.92,4977.97 ; U14.AM5@5471.7,5591.69 v2(5491.39,5611.37) ; v1(5491.39,5414.53) U14.AL13@5491.39,5434.21 U14.AL12@5491.39,5453.9 U14.AK11@5511.07,5473.58 5511.07,5473.93 v2(5491,5494) 5491.39,5494.39 U14.AL9@5491.39,5512.95 ; U14.AL3@5491.39,5631.06 v2(5491.39,5611.37) ; v3(5491.92,4995.97) 5491.92,4988.97 5502.92,4977.97 ; U14.AK5@5511.07,5591.69 v2(5491.39,5611.37) ; U14.AJ21@5530.42,5276.61 5530.42,5295.9 v3(5532.76,5298.24) 5532.76,5313.64 U14.AJ19@5530.43,5315.97 ; U14.AJ21@5530.43,5276.6 5532.97,5274.06 v3(5532.97,5257.46) 5530.43,5254.92 5530.43,5222.57 v3(5533,5220) ; v1(5530.76,5415.76) U14.AJ13@5530.76,5434.21 U14.AG11@5570.13,5473.58 5589.83,5473.58 U14.AE12@5609.5,5453.91 5603.91,5453.91 5593,5443 5593,5431.03 U14.AE14@5609.5,5414.53 ; D10.8@5547.14,4365.48 5548,4364.62 v1(5548,4341) ; U14.AH32@5550.12,5060.06 U14.AG33@5569.8,5040.38 ; U14.AH27@5550.11,5158.49 5557.44,5158.49 ; v2(5550.44,5512.95) 5550.44,5531.56 5550,5532 5550.44,5532.44 U14.AH7@5550.44,5552.32 U14.AG7@5570.13,5552.32 U14.AG6@5570.13,5572.01 ; v3(5555.44,4995.51) 5555.44,4988.49 5544.92,4977.97 ; U14.AG28@5569.81,5138.88 5569.81,5146.12 5557.44,5158.49 ; U14.AG25@5570.13,5197.99 5575.92,5192.2 v3(5575.92,5179.22) 5575.92,5176.97 5557.44,5158.49 ; U14.AG3@5570.13,5631.06 v2@5588.94,5631.06 ; U14.AE26@5609.5,5178.3 v1(5609.5,5197.99) v1(5609.5,5217.68) v1(5609.5,5237.36) v1(5609.5,5257.03) ; v1(5609.5,5335.78) v1(5609.5,5316.1) v1(5609.5,5296.4) ; v2(5610,5533) 5610,5513.45 U14.AE9@5609.5,5512.95 ; v3(5627.92,5129.97) 5638.77,5119.12 U14.AC29@5648.54,5119.12 ; U14.AD22@5629.18,5257.04 v1(5609.5,5257.03) ; U14.AD21@5629.18,5276.73 v1(5609.5,5276.73) ; U14.AD20@5629.18,5296.41 v1(5609.5,5296.4) ; U14.AD9@5629.19,5512.95 U14.AE9@5609.5,5512.95 ; v1@5642.81,5689.43 5648.79,5683.45 U14.AC1@5648.79,5670.41 ; U14.AC33@5648.54,5040.38 5633.92,5025.76 5633.92,4997.97 v3(5637.92,4993.97) 5637.92,4982.92 5632.97,4977.97 5544.92,4977.97 ; U14.AC26@5648.56,5178.25 5688.24,5178.25 5707.92,5178.25 5719.64,5178.25 5729.92,5167.97 5729.92,5161.19 U14.W27@5727.3,5158.57 ; U14.AB17@5668.55,5355.47 U14.AA16@5688.24,5375.16 U14.AA15@5688.24,5394.84 ; U14.AB14@5668.55,5414.53 U14.AB15@5668.55,5394.84 U14.AA15@5688.24,5394.84 ; U14.AB11@5668.55,5473.58 U14.AD11@5629.18,5473.58 5629.18,5493.27 U14.AE9@5609.5,5512.95 ; U14.AA30@5687.91,5099.43 5690.09,5097.25 v3(5706.21,5097.25) ; U14.Y10@5707.92,5493.27 5707.92,5483.77 5727.61,5464.08 U14.W12@5727.61,5453.9 U14.W13@5727.61,5434.21 ; U14.W16@5727.61,5375.16 5747.29,5355.48 ; U14.W15@5727.61,5394.84 U14.Y15@5707.92,5394.84 U14.AA15@5688.24,5394.84 ; X3.2@5729,4282 5752,4259 C265.2@5752,4246 ; U14.V19@5747.29,5316.1 U14.V18@5747.29,5335.78 5747.29,5355.47 v2(5766.98,5375.16) ; U14.U14@5765,5411.5 5766.98,5409.52 v2(5766.98,5375.16) ; U14.U25@5766.98,5197.98 v2(5749,5198) 5749,5171 5761.38,5158.62 U14.U27@5766.98,5158.62 ; U14.U25@5766.98,5197.98 U14.T24@5786.67,5217.67 U14.R24@5806.35,5217.67 U14.P24@5826.04,5217.67 5826.04,5235.04 5845.72,5254.72 U14.N22@5845.72,5257.04 ; U14.U7@5766.98,5552.31 v1(5787.08,5552.31) U14.R7@5806.34,5552.32 5823.68,5552.32 v1(5826,5550) ; C253.2@5774,4473 5773,4472 5765,4472 5755,4482 5755,4534.38 5762.62,4542 C254.2@5774,4542 5792,4560 5904,4560 5914,4550 5914,4536 C250.2@5912,4534 C249.2@5932,4534 5974.51,4534 R95.1@5976,4532.51 ; U14.T16@5786.67,5375.16 v2(5766.98,5375.16) ; U14.R27@5806.34,5158.62 U14.N27@5845.72,5158.62 ; U14.R19@5806.35,5316.1 U14.P19@5826.04,5316.1 U14.N19@5845.72,5316.1 ; U14.R11@5806.35,5473.58 U14.P11@5826.04,5473.58 ; U14.N30@5845.72,5099.56 v1(5865.72,5099.56) U14.L30@5885.09,5099.56 5904.77,5099.56 U14.J31@5924.46,5079.87 ; U14.N26@5845.72,5178.3 U14.N27@5845.72,5158.62 ; U14.N18@5845.72,5335.78 U14.N19@5845.72,5316.1 ; U14.N18@5845.72,5335.78 5845.72,5371.67 5842.23,5375.16 ; U14.N15@5845.72,5394.84 v2(5826.04,5375.16) 5842.23,5375.16 ; U14.N10@5845.72,5493.27 U14.P11@5826.04,5473.58 ; U14.N6@5845.72,5572.01 v1(5865,5572) U14.L6@5885.09,5572.01 U14.J6@5924.46,5572.01 ; U14.M18@5865.41,5335.78 U14.M19@5865.41,5316.1 ; U14.L24@5885.1,5217.67 U14.K25@5904.77,5197.99 ; U14.L19@5885.1,5316.1 U14.M19@5865.41,5316.1 ; U14.L10@5885.1,5493.27 U14.K10@5904.78,5493.27 ; U14.K15@5904.78,5394.84 U14.K16@5904.78,5375.16 ; U14.K9@5904.77,5512.95 U14.K10@5904.78,5493.27 ; v2(5924,5532) 5924.46,5531.54 U14.J9@5924.46,5512.95 U14.J10@5924.46,5493.26 ; U14.J28@5924.46,5138.93 U14.J26@5924.46,5178.3 ; U14.J23@5924.46,5237.36 U14.J22@5924.46,5257.03 U14.K22@5904.78,5257.04 U14.K21@5904.78,5276.73 U14.J21@5924.46,5276.73 ; U14.J13@5924.46,5434.21 U14.J12@5924.46,5453.91 ; v2(5943,5532) 5963.2,5532 U14.G8@5963.83,5532.64 U14.F8@5983.52,5532.64 ; U14.H24@5944.15,5217.67 U14.K24@5904.78,5217.67 U14.K25@5904.77,5197.99 U14.K26@5904.78,5178.3 5906,5177.08 5906,5166 5898.62,5158.62 U14.L27@5885.09,5158.62 U14.N27@5845.72,5158.62 ; U14.G28@5963.83,5138.93 U14.G29@5963.83,5119.25 5982.75,5119.25 v1(5983,5119) 6002.96,5119 U14.E29@6003.2,5119.25 ; U14.G18@5963.83,5335.78 5944.14,5355.47 U14.J17@5924.47,5355.47 U14.K16@5904.78,5375.16 ; U14.F24@5983.52,5217.67 U14.F22@5983.52,5257.04 v1(5983.52,5276) ; U14.F6@5983.52,5572.01 5984,5571.52 v1(5984,5552) 5984,5533.12 U14.F8@5983.52,5532.64 ; U14.D6@6022.89,5572.01 U14.C6@6042.57,5572.01 6042.57,5591.57 v1(6043,5592) ; R86.1@6023.47,4532.51 R82.1@6047,4532.51 ; U14.A1@6081.94,5670.43 6091,5679.49 v1(6091,5681) ; 6096.82,5490.65 v1(6117.75,5490.65) ; 6100.74,5161.78 6108.22,5161.78 v1(6110,5160) ; v1(6113.42,5326.69) v1@6113.84,5327.11 ; v3(4677.68,5267.64) 4677.84,5267.8 v3(4677.84,5298.97) ; 5502.92,4977.97 5544.92,4977.97 ; v1(5609.5,5257.03) v1(5609.5,5276.73) ; v1(5609.5,5276.73) v1(5609.5,5296.4) ; U14.P11@5826.04,5473.58 5836.42,5473.58 5845.72,5464.28 U14.N12@5845.72,5453.9 U14.M13@5865.41,5434.21 U14.L13@5885.09,5434.21 U14.L12@5885.1,5453.9 U14.K12@5904.78,5453.9 ; 5842.23,5375.16 U14.M16@5865.41,5375.16 U14.L16@5885.09,5375.16 U14.K16@5904.78,5375.16 ; U14.N19@5845.72,5316.1 U14.M19@5865.41,5316.1 ; U14.K12@5904.78,5453.9 U14.K11@5904.78,5473.58 U14.K10@5904.78,5493.27 ; U14.K12@5904.78,5453.9 U14.J12@5924.46,5453.91 ; U14.K10@5904.78,5493.27 U14.J10@5924.46,5493.26 ; U14.J12@5924.46,5453.91 5924.46,5471.97 ; 5924.46,5471.97 5961.97,5471.97 v2(5963,5473) 5963.82,5473.82 U14.G10@5963.82,5493.27 ; 5924.46,5471.97 U14.J10@5924.46,5493.26 ; U14.J10@5924.46,5493.26 U14.G10@5963.82,5493.27 ; U14.G10@5963.82,5493.27 U14.F10@5983.52,5493.27 5983.52,5511.48 v2(5983,5512) 5983,5532.12 U14.F8@5983.52,5532.64
  Top Layer w20: R6.1@3985.27,4614.78 4044.49,4614.78 CN4.1@4064.91,4635.2 ; USB3.13@6549.92,6194.73 6557.01,6194.73 USB3.B1A12@6593.03,6158.7 ; USB3.A1B12@6846.97,6158.7 6854.06,6158.7 USB3.12@6890.08,6194.73
  GND1 w3: 4702.92,5453.97 4704.92,5451.97 4716.92,5451.97 4718.92,5453.97 ; 4732.92,5121.97 4734.62,5121.97 4735.6,5122.95 4745.96,5122.95 4746.94,5121.97 4750.92,5121.97
  内层2 w6: v2(5435,4495) 5649,4709 5996,4709 6025,4738 6025,4797 6163.68,4935.68 6174.68,4935.68 v2(6179,4940) ; v2(5491.39,4493.87) 5491.39,4504.72 5662.68,4676 6012,4676 6058,4722 6058,4788 6172,4902 6271,4902 v2(6292,4923) ; v2(5548,4494) 5550.51,4494 5552,4495.49 5552,4507 5685,4640 6196.85,4640 6222,4665.15 v2(6222,4676)
  内层4 w6: v1(5103,4318) 5103,4359 5162,4418 5162,4524 5241,4603 5645,4603 5704,4662 6094,4662 6167,4589 6314,4589 6388,4663 6388,5033.87 6343.87,5078 v1(6333,5078) ; v2(5158,4322) 5158,4361 5197,4400 5197,4513 5254,4570 5672,4570 5730,4628 6078,4628 6151,4555 6335,4555 6420,4640 6420,5062 6363,5119 6329,5119 v1(6328,5120) ; v1(5216,4318) 5216,4347 5231,4362 5231,4498 5272,4539 5689,4539 5739,4589 6074,4589 6139,4524 6351,4524 6453,4626 6453,5082 6377,5158 v1(6335,5158)
  Bottom Layer w4: 3750,5429 3772,5406
  Bottom Layer w6: 4425,4229 4421,4225 4421,4151 v2(4428,4144) ; 4995,4736 4995.5,4736.5 4995.5,4755 ; 5365.46,5778.12 5365.77,5777.81 5365.77,5729.23 5417,5678 v1(5439,5678) ; v2(5670,5552) 5676,5546 5713,5546 5720.5,5538.5 5720.5,5533 ; 5765,5411.5 5783,5393.5 5783,5391.18 v2(5766.98,5375.16) 5766.98,5333.98 5764,5331 5806,5331 5807,5332 5843.16,5332 ; 5784.5,5664 5792,5664 5802,5654 5802,5563 5791.31,5552.31 v1(5787.08,5552.31) ; 5787.75,5495.75 5911.75,5495.75 5915.5,5492 5915.5,5513 ; 5844.5,5375 5844.5,5333.34 5843.16,5332 ; 5847.5,5332 5843.16,5332 ; 5944.49,5171.53 5944.49,5197 ; 5982.51,5218 5982.51,5258.47 5983.52,5259.48 v1(5983.52,5276) ; 6803.51,5340.31 6803.51,5374.51 6817,5388 6848,5388 6868,5368 6868,5306.5
  Bottom Layer w8: v2(3732,5431) 3748,5431 3750,5429 ; v3(4679.84,5335.97) 4690.42,5346.55 4690.42,5357.89 v3(4681.32,5366.99) ; v3(4931.79,5366.86) 4935.42,5363.23 4935.42,5345.97 ; RJ1.SHIELD0@6308.76,3833.5 6331,3811.26 6331,3771 6350,3752 v1(6350,3745) ; v1(6647,4156) v1(6725,4156) 6867,4156 6911,4200
  Bottom Layer w10: 3497,5504.99 3535.73,5504.99 3536.01,5504.72 3536.01,5470 ; 3505.21,5618.33 3505.53,5618.01 3604,5618.01 ; 4425,4229 4737,4541 5091,4541 5218,4668 5981,4668 6152,4839 v1(6187,4839) ; v2@4478,4204 4478,4216 4757,4495 5102,4495 5245,4638 6320,4638 6375,4693 6375,4756 v2(6336,4795) ; v2(4536,4204) 4790,4458 5123,4458 5267,4602 6344,4602 6454,4712 6454,4899 6353,5000 6289,5000 6229,5060 6229,5167 v2(6195,5201) ; v3(4646.77,5084.95) 4658.82,5072.9 4658.82,5060.67 ; 4693,5201 v3(4709.98,5211.02) ; v3(4706.92,5110.97) 4711.92,5105.97 4738.92,5105.97 4748.92,5115.97 4769.08,5115.97 ; 4715.92,5596.47 4730.42,5596.47 v3(4735.92,5601.97) ; v3(4738.92,5188.97) 4742.42,5192.47 4742.42,5207.97 ; v3(4739.91,5265.01) 4749.95,5265.01 4766.07,5281.13 4767.92,5281.13 ; 4768.8,5467.31 4768.8,5450.77 v3(4774.25,5445.32) ; v3(4836.92,5181.97) 4836.92,5178.47 4852.42,5162.97 ; 4843.76,5200.97 4857.84,5200.97 v3(4861.84,5204.97) ; 4852.8,5402.68 4870.1,5419.98 v3(4870.1,5423.94) ; v2(4873,4768) 4876.5,4764.5 4876.5,4749 ; 4903.76,5596.97 4944.92,5596.97 v3(4955.92,5607.97) ; 4917.92,5249.81 4917.92,5251.97 v3(4930.92,5264.97) ; 4924.08,5440.97 4924.08,5459.13 v3(4930.92,5465.97) ; v3(4929.92,5086.97) 4937.42,5094.47 4937.42,5109.97 ; v3(4940.28,5028.72) 4943.94,5025.06 4943.94,5007.06 4942.94,5006.06 ; 5016.42,5186.97 5017.42,5185.97 v3(5034.92,5185.97) 5049.92,5200.97 5054.08,5200.97 ; 5024.08,5500.97 5024.08,5486.33 v3(5029.92,5480.49) ; v3(5024.22,5154.7) 5030.33,5160.81 5048.92,5160.81 ; 5379.92,5183.97 5381.77,5183.97 5387.92,5177.83 ; v3(5398.92,5161.97) 5387.92,5172.97 5387.92,5177.83 ; 5417.92,5187.13 5416.92,5186.13 5387.92,5186.13 5387.92,5177.83 ; 5451.49,5630.17 5464.92,5616.74 5486.03,5616.74 v2(5491.39,5611.37) 5520.11,5611.37 5521.87,5613.13 ; 5469.5,5494 v2(5491,5494) ; 5561.65,5439.18 5582.52,5439.18 5582.68,5439.35 5584.5,5437.54 5584.5,5397 5626.88,5397 5627.25,5397.38 5643.28,5397.38 5655.85,5384.81 5757.33,5384.81 v2(5766.98,5375.16) ; 5570,5626.5 5571.65,5626.5 5576.15,5631 v2(5589,5631) ; 5613.5,5513 5613.5,5529.5 v2(5610,5533) 5644,5533 ; v3(5627.92,5129.97) 5627.92,5142.47 ; 5629,5156.5 5627.92,5155.42 5627.92,5142.47 ; 5631.5,5568 5629,5565.5 5629,5548 5644,5533 ; 5647.5,5533 5644,5533 ; 5667,5362 5744.07,5362 5745.11,5360.97 ; 5668.92,5178.47 5647.92,5178.47 5647.92,5147.97 5644.92,5144.97 5630.42,5144.97 5627.92,5142.47 ; v2(5688,5237) 5688,5291 5694,5297 ; 5707.92,5178.47 5721.42,5178.47 5729.92,5169.97 5729.92,5160.97 v3(5727.92,5158.97) ; 5715,5610 5699,5626 5699,5652 5711.5,5664.5 5716,5664.5 ; 5748,5234 5749,5233 5749,5214.13 ; v2(5749,5198) 5749,5214.13 ; v1(5752,4178) 5773,4157 v1(5930,4157) v1(6010,4157) ; 5790.5,5137 5790.5,5179 5810.5,5179 5815,5183.5 5815.7,5182.8 5829.84,5182.8 5837.14,5175.5 5841,5175.5 ; 5809,5214 5787,5214 5786.87,5214.13 5749,5214.13 ; 5844.5,5375 5844.34,5375.16 v2(5826.04,5375.16) 5844.5,5393.62 5844.5,5395 ; 5883.5,5272 5883.5,5253 5904.5,5253 ; 5888.5,5452 5915,5452 ; 5888.5,5473 5914,5473 5915,5472 5915,5452 ; 5904,5253.5 5904.5,5253 ; 5906.5,5233 5906.5,5251 5904.5,5253 ; 5915,5433 5915,5452 ; 5925,5253.5 5924.5,5253 5904.5,5253 ; 5960,5369 5960,5413 ; v2(6204,5526) 6467,5526 v2(6522,5471) 6599,5394 v2(6599,5255) 6598,5254 6598,5019 6651,4966 6651,4840 6713.59,4777.41 7072.02,4777.41 ; v2(6243,5565) 6483,5565 v2(6518,5530) 6640,5408 6640,5056 6674,5022 7030,5022 7038.36,5013.64 7072.02,5013.64 ; v2(6282,5630) 6282,5623 6311,5594 6495,5594 6675,5414 6675,5094 6715.99,5053.01 7072.02,5053.01 ; v2(6531,5393) 6531,5390 6522,5381 6522,5274 v2(6541,5255) 6541,5005 6607,4939 6607,4801 6689.64,4718.36 7072.02,4718.36 ; v1(7195,5831) 7226.02,5862.02 7238.14,5862.02
  Bottom Layer w20: 7139,4392.61 7144.99,4398.6 7144.99,4455.28
  Bottom Layer w30: RJ1.SHIELD1@5678,3834.26 RJ1.SHIELD0@6308,3834.26 ; RJ1.P10@6213.9,3964.16 6213.9,3928.36 RJ1.SHIELD0@6308,3834.26 ; RJ2.P10@6932.9,3963.4 6932.9,3927.6 RJ2.SHIELD0@7027,3833.5 RJ2.SHIELD1@6397,3833.5 6308.76,3833.5 RJ1.SHIELD0@6308,3834.26
  other v1: 6353,3505 6326,3625 6375,3625 5548,4341 4005.9,5137.74 3972,5172 4006,5172 6110.87,5243.47 6713,5580 6713,5603 6727,5681 5640.43,5689.43 6727,5704
  other v2: 4478,4200.58 6527,4262.5 5797,4268.47 6636.91,4287.95 6668.91,4287.95 6700.91,4287.95 6732.91,4287.95 5922,4298.5 5954,4298.5 5986,4298.5 6018,4298.5 6636.91,4317.95 6668.91,4317.95 6700.91,4317.95 6732.91,4317.95 5922,4328.5 5954,4328.5 5986,4328.5 6018,4328.5 6636.91,4348.95 6668.91,4348.95 6700.91,4348.95 6732.91,4348.95 5922,4359.5 5954,4359.5 5986,4359.5 6018,4359.5 6636.91,4376.95 6668.91,4376.95 6700.91,4376.95 6732.91,4376.95 5922,4387.5 5954,4387.5 5986,4387.5 6018,4387.5 5623,4494 6247,4709 6247,4764 6217,4807 6153,4824 6240,4864 6304,4891 6918,4896 6096,4921 6079,4952 3721,4977 6470,5420 3643,5456 3675,5456 3643,5486 3675,5486 3707,5486 3739,5486 3643,5517 3675,5517 3707,5517 3739,5517 3643,5545 3675,5545 3707,5545 3739,5545 4173.04,5793 4223,5793 3659,5886 3695,5886 3733,5889 3625,5891 3760,5907 3611,5911 3780,5927 3857,5940 3801,5941 3827,5941 3883,5941 3916,5941 3611,5942 3765,5953 3786,5964 3817,5965 3840,5966 3873,5968 3923,5968 3899,5969 3610,5975 3610,5998 3826,6009 3897,6009 3805,6010 3866,6010 3921,6010 3608,6026 3854,6036 3880,6037 3910,6037 3799,6038 3772,6039 3825,6039 3748,6042 3608,6057 3805,6065 3768,6069 3614,6078 3739,6078 3633,6085 3668,6088 3700,6090
  other v4: 3825.32,4760.31 3864.68,4760.31 3825.32,4799.69 3864.68,4799.69
HBIAS: U14.AL1 | length 1197.6
  Top Layer w8: U14.AL1@5491.39,5670.43 5494,5673.04 5494,5712 v1(5502,5720)
  内层2 w10: v1(5866,6198) 5909.51,6154.49 v1(6174,6154.49)
  GND2 w10: v1(5502,5720) 5508,5726 5508,6049 5569,6110 5804,6110 5866,6172 v1(5866,6198)
  Bottom Layer w5: 6144.76,6179.98 6144.76,6160.49 6150.76,6154.49 v1(6174,6154.49)
HCEC: D7.1 R48.1 U14.E28 | length 1948.4
  Top Layer w4: U14.E28@6003.2,5138.93 v1(6003.2,5158.93)
  Top Layer w5: D7.1@4866,4310 4866,4338 4881.51,4353.51 R48.1@4936,4353.51 4937,4354.51 v1(4937,4370)
  Inner5 w5: v1(4937,4370) 4973,4406 5006,4406 5023,4423 5066,4423 5079,4436 5096,4436 5216,4556 5683,4556 5721,4594 5891,4594 6030,4733 6030,4798 6125,4893 6125,5119 6115,5129 6096,5129 6081,5144 6018.14,5144 v1(6003.2,5158.93)
HHPD: C189.2 R54.1 U14.D28 | length 1761.4
  Top Layer w4: U14.D28@6022.89,5138.93 v1(6022.89,5158.93)
  Top Layer w5: R54.1@5044,4353.51 C189.2@5044,4371 ; C189.2@5044,4375 C189.2@5044,4371 ; v1(5092,4418) 5091,4418 C189.2@5044,4371
  Inner5 w5: v1(5092,4418) 5104,4418 5226,4540 5691,4540 5729,4578 5901,4578 6045,4722 6045,4789 6140,4884 6140,5125 6121,5144 6101,5144 6086.07,5158.93 v1(6022.89,5158.93)
HP-DET: CN2.3 U14.AJ2 | length 1020.9
  Top Layer w3: v1(5516,5706) 5520.87,5701.13 5520.87,5662.57 U14.AJ2@5531.53,5651.91
  Top Layer w6: v1(5975,6258) 6027.64,6310.64 CN2.3@6034.42,6310.64
  GND2 w6: v1(5516,5706) 5524,5714 5524,6041 5579,6096 5813,6096 v1(5975,6258)
HPOUTFB: CN2.6 U14.AM1 | length 1672.9
  Top Layer w3: 5459.2,5708.02 5459.2,5690.01 5471.59,5677.62 U14.AM1@5471.59,5670.41
  Top Layer w10: v1(5458,5728) 5458,5709.22 5459.2,5708.02 ; v1(5814,6188) 5814,6178 5831,6161 6015,6161 6069,6215 6087,6215 6099.76,6227.76 v1(6099.76,6235.76) 6213.24,6235.76 6254,6195 6254,6050 6328.01,5975.99 CN2.6@6351.58,5975.99
  GND2 w10: v1(5458,5728) 5474,5744 5474,6073 5549,6148 5774,6148 v1(5814,6188)
  Bottom Layer w10: 6074.76,6200 6099.76,6200 v1(6099.76,6235.76) 6108,6244 6121.75,6244 6122.76,6242.99
HPOUTL: CN2.5 U14.AL2 | length 1441.8
  Top Layer w3: 5480,5690 5480,5681.65 5481.41,5680.24 5481.41,5660.59 U14.AL2@5491.29,5650.71
  Top Layer w10: 5480,5690 5480,5725 v1(5482,5727) ; v1(5842,6178) 6010,6178 6055,6223 v1(6055,6239) 6073,6257 6221,6257 6269.73,6208.27 CN2.5@6351.58,6208.27
  GND2 w10: v1(5482,5727) 5491,5736 5491,6061 5561,6131 5795,6131 v1(5842,6178)
  Bottom Layer w10: 6030.99,6198 6055,6222.01 v1(6055,6239)
HPOUTR: CN2.2 U14.AM2 | length 1286.7
  Top Layer w3: 5442,5704 5447,5699 5447,5691 5462.03,5675.97 ; 5462.02,5675.96 5462.02,5663.42 5471.29,5654.15 U14.AM2@5471.29,5652.24
  Top Layer w10: v1(5436,5721) 5438,5719 5438,5708 5442,5704 ; v1(5776,6179) 5790.14,6179 5825.14,6144 6018,6144 6061,6101 v1(6061,6094) 6061,6065.56 CN2.2@6034.42,6038.98
  GND2 w10: v1(5436,5721) 5436,5733 5457,5754 5457,6085 5539,6167 5764,6167 v1(5776,6179)
  Bottom Layer w10: 6030.72,6163.85 6061,6133.57 v1(6061,6094)
HREXT: U14.F26 | length 40.6
  Top Layer w4: U14.F26@5983.52,5178.3 v1(5983.52,5198.3)
  Bottom Layer w10: 5963.51,5197 5982.23,5197 v1(5983.52,5198.3)
HS-MIC: CN2.4 | length 325.6
  Top Layer w10: v1(6281,6302) 6329.01,6350.01 CN2.4@6351.58,6350.01
  Bottom Layer w5: 6122.76,6199.49 6123.19,6199.06
  Bottom Layer w10: 6122.76,6199 6122.76,6199.49 6122.76,6220.49 ; 6123.19,6199.06 6144.69,6199.06 ; 6144.76,6199 6144.76,6220.49 6149.49,6220.49 6166,6237 6216,6237 v1(6281,6302)
HSCL: R50.1 U14.D26 | length 1902
  Top Layer w4: U14.D26@6022.89,5178.3 v1(6022.89,5198.3)
  Top Layer w5: R50.1@4959,4353.51 v1(4959,4370)
  Inner5 w5: v1(4959,4370) 4977,4388 5015,4388 5030,4403 5112,4403 5235,4526 5700,4526 5737,4563 5906,4563 6059,4716 6059,4783 6152,4876 6152,5151 6120,5183 6044,5183 6028.7,5198.3 v1(6022.89,5198.3)
HSDA: R51.1 U14.E26 | length 1929.4
  Top Layer w4: U14.E26@6003.2,5178.3 v1(6003.2,5198.3)
  Top Layer w5: R51.1@5002,4353.51 v1(5002,4372)
  Inner5 w5: v1(5002,4372) 5034,4372 5051,4389 5116,4389 5238,4511 5707,4511 5745,4549 5916,4549 6074,4707 6074,4776 6165,4867 6165,5158 6124.7,5198.3 6044.7,5198.3 6029,5214 6018.9,5214 v1(6003.2,5198.3)
HTX0N: D6.2 D6.9 U14.C27 USB1.9 | length 2876.9
  Top Layer w3: U14.C27@6042.49,5158.51 6042.71,5158.51 6047.82,5153.4 ccw(c6059.14,5164.71) 6059.14,5148.71 6084.98,5148.71 cw(c6084.98,5144.56) 6087.92,5147.49 6095.37,5140.02 6154,5140.02 cw(c6154,5096.6) 6185,5127
  Top Layer w4: USB1.9@5062.26,3878.43 5064.57,3878.43 5081.67,3861.33 5087.33,3861.33 5128.53,3902.53 5128.53,4243.46 5122.7,4249.28 D6.9@5122.7,4264.67 D6.2@5122.7,4299.33 5126,4302.63 5126,4328 v1(5121,4333) ; 6185,5126.29 6198.91,5112.38 ccw(c6228.82,5142.29) 6227.81,5100 6266.95,5099.06 cw(c6266.95,5080.99) v1(6282,5091)
  内层4 w4: v1(5121,4333) 5121,4342.87 5126.99,4348.87 5126.99,4358.99 5176,4408 5176,4521.34 5243.68,4589.02 5660.02,4589.02 5719.02,4648.02 6088.98,4648.02 6162.33,4574.67 6322.67,4574.67 6399,4651 6399,5052 6353,5098 6289,5098 v1(6282,5091)
HTX0P: D6.1 D6.10 U14.B27 USB1.7 | length 2878.3
  Top Layer w3: U14.B27@6061.55,5157.9 ccw(c6072.62,5175.49) 6072.62,5154.71 6084.98,5154.71 cw(c6084.98,5144.56) 6092.17,5151.73 ; 6092.17,5151.72 6096.85,5147.03 ccw(c6098.28,5237.21) 6098.28,5147.02 6154,5147.02 cw(c6154,5096.6) 6190,5131.9
  Top Layer w4: USB1.7@5062.26,3832.97 5080.29,3850.98 5088.32,3850.98 5136.54,3899.21 5136.54,4243.46 5142.37,4249.28 D6.10@5142.37,4264.67 D6.1@5142.37,4299.33 5138,4303.7 5138,4330 v1(5141,4333) ; 6190.71,5131.9 6204.57,5118.04 ccw(c6228.82,5142.29) 6228,5108 6267.15,5107.06 ccw(c6267.15,5137.03) v1(6282,5111)
  内层4 w4: v1(5141,4333) 5141,4342.87 5135.01,4348.87 5135.01,4357.11 5183,4405.1 5183,4517 5247,4581 5663.34,4581 5722.34,4640 6084,4640 6157.35,4566.65 6325.99,4566.65 6407,4647.66 6407,5055.34 6356.32,5106.02 6286.98,5106.02 v1(6282,5111)
HTX1N: D5.5 D5.6 U14.B26 USB1.6 | length 3067.3
  Top Layer w3: U14.B26@6061.86,5177.79 cw(c6062.5,5167.62) 6070.44,5174 ccw(c6083.62,5184.6) 6077.93,5168.67 ccw(c6081.58,5178.89) 6088.2,5170.29 cw(c6098.5,5156.92) 6098.5,5173.8 6115.13,5173.8 cw(c6115.13,5160.79) 6124.33,5169.99 6127.47,5166.85 ccw(c6141.62,5181) 6141.62,5160.99 6174,5160.99
  Top Layer w4: USB1.6@5022.89,3809.96 USB1.6@5023.85,3809 ; USB1.6@5022.89,3809.96 5074,3810 5086,3798 5090,3798 5183,3891 5183,4049.92 5211.98,4078.91 5211.98,4199.15 5182.46,4228.68 5182.46,4243.46 5176.63,4249.28 D5.6@5176.63,4264.67 D5.5@5176.63,4299.32 5180,4302.69 5180,4329 v1(5177,4332) ; 6174.5,5160.49 6199.02,5160.49 cw(c6199.02,5112.98) 6230,5149 ccw(c6276.9,5203.53) 6284.89,5132.05 cw(c6284.89,5112.5) v1(6298,5127)
  内层4 w4: v1(5177,4332) 5177,4341.87 5182.49,4347.37 5182.49,4353.02 5187.27,4357.8 5187.27,4363.46 5186.69,4364.03 5186.69,4369.69 5191.64,4374.64 5197.3,4374.64 5197.87,4374.06 5203.53,4374.06 5212.98,4383.52 5212.98,4406.66 5207.98,4411.66 5207.98,4421.66 5212.98,4426.66 5212.98,4436.66 5207.98,4441.66 5207.98,4451.66 5212.98,4456.66 5212.98,4466.66 5207.98,4471.66 5207.98,4481.66 5212.98,4486.66 5212.98,4506.32 5263.68,4557.02 5678.02,4557.02 5734,4613 6076.98,4613.02 6147,4543 6340,4543 6433,4636 6433,5070 6369,5134 6305,5134 v1(6298,5127)
HTX1P: D5.4 D5.7 U14.A26 USB1.4 | length 3066.9
  Top Layer w3: U14.A26@6081.89,5178.21 6083.39,5179.71 cw(c6086.02,5177.08) 6086.02,5180.8 6115.13,5180.8 cw(c6115.13,5160.78) 6129.28,5174.94 6132.42,5171.8 ccw(c6141.62,5181) 6141.62,5167.99 6174.05,5167.99 ccw(c6174.05,5183.72) 6177.98,5168.49
  Top Layer w4: USB1.4@5022.89,3764.45 5077.45,3764.45 5095,3782 5095,3791.66 5191,3887.66 5191,4046.59 5220,4075.59 5220,4202.47 5190.47,4232 5190.47,4243.46 5196.3,4249.28 D5.7@5196.3,4264.67 D5.4@5196.3,4299.33 5192,4303.63 5192,4327 v1(5197,4332) ; 6174.55,5168.49 6177.98,5168.49 6199.02,5168.49 cw(c6199.02,5112.98) 6235.22,5155.07 ccw(c6276.9,5203.53) 6284,5140 ccw(c6284,5154.56) v1(6297,5148)
  内层4 w4: v1(5197,4332) 5197,4340.87 5190.51,4347.37 5190.51,4349.37 5221,4379.86 5221,4503 5267,4549 5681.34,4549 5737.34,4605 6073,4605 6143.02,4534.98 6343.32,4534.98 6440,4631.66 6440,5076 6373,5143 6302,5143 v1(6297,5148)
HTX2N: D5.2 D5.9 U14.C25 USB1.3 | length 3265
  Top Layer w3: U14.C25@6042.49,5197.91 6047.6,5192.8 ccw(c6058.92,5204.11) 6058.92,5188.11 6126.07,5188.11 cw(c6126.07,5173.31) 6136.54,5183.77 6136.87,5183.44 ccw(c6147.54,5194.11) 6147.54,5179.02 6175.61,5179.02 ; 6181,5179.02 6175.61,5179.02 ; 6181.5,5178.52 ccw(c6175.61,5144.12) 6175.61,5179.02
  Top Layer w4: USB1.3@5062.26,3742 5062.26,3735.76 5076,3722.02 5099.98,3722.02 5136,3686 5191,3686 5241.53,3736.53 5241.53,4243.46 5235.7,4249.28 D5.9@5235.7,4264.67 D5.2@5235.7,4299.33 5240,4303.63 5240,4328 v1(5236,4332) ; 6181.5,5178.52 6203.51,5178.52 cw(c6203.51,-31) 6277,5178 6296,5177.73 cw(c6296,5154.81) v1(6314,5169)
  内层4 w4: v1(5236,4332) 5236,4341.87 5242.32,4348.2 5242.32,4491.66 5280.68,4530.02 5695.68,4530.02 5741.66,4576 ; 5741.68,4576.02 6072.3,4576.02 6134.31,4514 6362,4514 6465,4617 6465,5092.1 6382.1,5175 6320,5175 v1(6314,5169)
HTX2P: D5.1 D5.10 U14.B25 USB1.1 | length 3262.3
  Top Layer w3: U14.B25@6062.19,5197.91 6063.79,5196.31 ccw(c6066.64,5199.16) 6066.64,5195.13 6128.93,5195.13 cw(c6128.93,5180.28) 6139.43,5190.78 6141.82,5188.39 ccw(c6147.54,5194.11) 6147.54,5186.02 6178.65,5186.02 ; 6182.02,5186.02 6178.65,5186.02 ; 6182.03,5186.02 ccw(c6178.55,-4817.88) 6178.66,5186.02
  Top Layer w4: USB1.1@5062.26,3696.54 5062.26,3700.26 5076,3714 5096.66,3714 5132.68,3677.98 5194.32,3677.98 5249.54,3733.21 5249.54,4243.46 5255.37,4249.28 D5.10@5255.37,4264.67 D5.1@5255.37,4299.33 5251,4303.7 5251,4326.34 v1(5256.66,4332) ; 6182.52,5186.52 6203.51,5186.52 cw(c6203.51,-31) 6277.11,5186 6296.11,5185.73 ccw(c6296.11,5236.33) v1(6314,5189)
  内层4 w4: v1(5256.66,4332) 5256.66,4341.87 5250.34,4348.2 5250.34,4488.34 5284,4522 5699,4522 5745,4568 6069,4568 6131.02,4505.98 6365.32,4505.98 6473.02,4613.68 6473.02,5093.98 6384,5183 6320,5183 v1(6314,5189)
HTXCN: D6.5 D6.6 U14.B28 USB1.12 | length 2784.9
  Top Layer w3: U14.B28@6062.19,5138.91 6067.59,5133.51 ccw(c6078.21,5144.12) 6078.21,5129.11 6087.21,5129.11 6092.3,5124.02 6133.3,5124.02 cw(c6133.3,3512.36) 6141,5124 6145.7,5124.01 cw(c6145.7,5115.9) 6152,5121
  Top Layer w4: USB1.12@5022.89,3946.5 5075.5,3946.5 5087,3935 5091,3935 5100,3944 5100,4207.59 5069.46,4238.14 5069.46,4243.46 5063.63,4249.28 D6.6@5063.63,4264.67 D6.5@5063.63,4299.32 5067,4302.69 5067,4330 v1(5064,4333) ; 6152,5121 cw(c6096.03,5010.28) 6186.19,5095.5 ccw(c6219.89,5127.36) 6221,5081 cw(c6222.13,5033.84) 6255.36,5067.32 ccw(c6290.13,5102.35) 6290.13,5053 6292.13,5053 cw(c6292.13,5029.16) v1(6309,5046)
  内层4 w4: v1(5064,4333) 5064,4342.87 5070.49,4349.37 5070.49,4354.69 5074.36,4358.56 ccw(c5069.91,4363.01) 5074.36,4367.46 cw(c5078.81,4371.91) 5074.36,4376.36 5076.07,4378.07 cw(c5080.52,4373.61) 5084.97,4378.07 ccw(c5089.42,4382.52) 5093.87,4378.07 5141,4425.19 5141,4544.34 5217.68,4621.02 5631.02,4621.02 5693.02,4683.02 6102.98,4683.02 6174,4612 6302,4612 6367,4677 6367,5024 6338,5053 6316,5053 v1(6309,5046)
HTXCP: D6.4 D6.7 U14.A28 USB1.10 | length 2786.1
  Top Layer w3: U14.A28@6081.94,5138.93 6083.5,5137.3 ccw(c6086.37,5140.16) 6086.37,5136.11 6090.11,5136.11 6095.2,5131.02 6145.7,5131.01 cw(c6145.7,5112.46) 6155.61,5128.14
  Top Layer w4: USB1.10@5022.89,3900.97 5023.91,3902 5079,3902 5089,3912 5089,3918 5108.02,3937.02 5108.02,4210.91 5077.47,4241.46 5077.47,4243.46 5083.3,4249.28 D6.7@5083.3,4264.67 D6.4@5083.3,4299.33 5081,4301.63 5081,4329 v1(5085,4333) ; 6155.61,5128.14 cw(c6096.03,5010.28) 6192,5101 ccw(c6219.89,5127.36) 6220.81,5089 cw(c6222.13,5033.84) 6261,5073 ccw(c6290.13,5102.35) 6290.13,5061 6292.13,5061 ccw(c6292.13,5084.84) v1(6309,5068)
  内层4 w4: v1(5085,4333) 5085,4342.87 5078.51,4349.37 5078.51,4351.37 5148,4420.86 5148,4540 5221,4613 5634.34,4613 5696.34,4675 6098,4675 6169.02,4603.98 6305.32,4603.98 6375.02,4673.68 6375.02,5027.32 6341.34,5061 6316,5061 v1(6309,5068)
IR-RX: CGQ1.3 R124.1 U14.AL16 | length 5146.7
  Top Layer w3: U14.AL16@5491.39,5375.16 5510.16,5375.16 v2(5511,5376)
  Top Layer w6: R124.1@7052.62,4115.95 7052.62,4094.62 v2(7052,4094) 7052,4089 7084,4057 7194,4057 7210.88,4073.88 CGQ1.3@7210.88,4113.94
  内层2 w4: v2(5112,5732) 5134,5710 5152,5710 5192,5670 5304,5670 5375,5599 5375,5483.58 5476.58,5382 5505,5382 v2(5511,5376)
  内层4 w6: v2(5064,6014) 5127,6077 5419,6077 5621,5875 5755,5875 5810,5820 6745,5820 6857,5708 6857,5568 6798,5509 6798,4772 7076,4494 7126,4494 7248,4372 7248,4215 7205,4172 7130,4172 v2(7052,4094)
  Bottom Layer w4: v2(5064,6014) 5074,6004 5074,5979 5082,5971 5082,5823 5128,5777 5128,5748 v2(5112,5732)
LCD0-CLK: U14.K31 | length 2944.3
  Top Layer w3: U14.K31@5904.64,5079.71 5914.45,5065.42 5915.07,5056.38 5914.99,5041.24 5914.45,5032.98 5915.07,5021.24 5914.22,5003.55 5917.93,4993.2 5918.93,4973.19
  Top Layer w4: v1(4423,4395) 4423,4428 4396,4455 4396,4476 4412,4492 4477,4492 4502,4467 5044,4467 5289,4712 5490,4712 5550,4772 5742,4772 5811,4841 5819,4841 5882,4904 5885,4904 5919,4938 5919,4973
  Bottom Layer w5: 3564.97,4120.52 3632.51,4120.52 3732,4220 4149,4220 4198,4269 4243,4269 4369,4395 v1(4423,4395)
LCD0-D0: U14.N28 | length 2757.5
  Top Layer w5: U14.N28@5845.72,5138.93 v1(5865.72,5138.93)
  内层2 w5: v1(4719,4824) 4828,4715 5460,4715 5572,4827 5808,4827 5909,4928 5909,5060 5884,5085 5858,5085 5851,5092 5851,5124.22 v1(5865.72,5138.93)
  Bottom Layer w5: 3564.97,4829.18 3566.97,4831.18 4711.82,4831.18 v1(4719,4824)
LCD0-D1: U14.N29 | length 2746.6
  Top Layer w5: U14.N29@5845.72,5119.25 v1(5865.72,5119.25)
  内层2 w5: v1(4719,4801) 4820,4700 5471,4700 5583,4812 5813,4812 5924,4923 5924,5065 5869.75,5119.25 v1(5865.72,5119.25)
  Bottom Layer w5: 3564.97,4809.48 3801.68,4809.48 3810.2,4818 4702,4818 v1(4719,4801)
LCD0-D2: U14.D32 | length 2780.5
  Top Layer w3: U14.D32@6022.88,5060.51 6032.77,5050.61 6032.77,5030.23 6050,5013 6050,4966 v1(6055,4961)
  内层2 w5: v1(4720,4776) 4812,4684 5480,4684 5592,4796 5868,4796 6033,4961 v1(6055,4961)
  Bottom Layer w5: 3564.97,4789.81 3797.2,4789.81 3807,4780 3878,4780 3901,4803 4693,4803 v1(4720,4776)
LCD0-D3: U14.D33 | length 2780
  Top Layer w3: U14.D33@6022.85,5040.79 6022.85,5026.85 6041,5008.7 v1(6041,4945)
  内层2 w5: v1(4720,4752) 4807,4665 5483,4665 5599,4781 5877,4781 v1(6041,4945)
  Bottom Layer w5: 3564.97,4770.11 3787.89,4770.11 3819,4739 3869,4739 3905,4775 3905,4776 3917,4788 4684,4788 v1(4720,4752)
LCD0-D4: U14.E30 | length 2782.8
  Top Layer w5: U14.E30@6003.2,5099.56 v1(6022.2,5099.56)
  Bottom Layer w5: 3564.97,4750.44 3775.57,4750.44 3804,4722 3883,4722 3933,4772 4673,4772 4761,4684 5017,4684 5129,4796 5601,4796 5750,4945 5750,5017 5806,5073 5891,5073 5903,5061 5998.32,5061 6008,5070.68 6008,5093.57 6013.99,5099.56 v1(6022.2,5099.56)
LCD0-D5: U14.E31 | length 2778.9
  Top Layer w5: U14.E31@6003.2,5079.88 v1(6022.2,5079.88)
  Bottom Layer w5: 3564.97,4730.74 3770.26,4730.74 3796,4705 3890,4705 3942,4757 4662,4757 4753,4666 5025,4666 5137,4778 5607,4778 5769,4940 5769,5012 5815,5058 5886,5058 5898,5046 6004,5046 6022.2,5064.2 v1(6022.2,5079.88)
